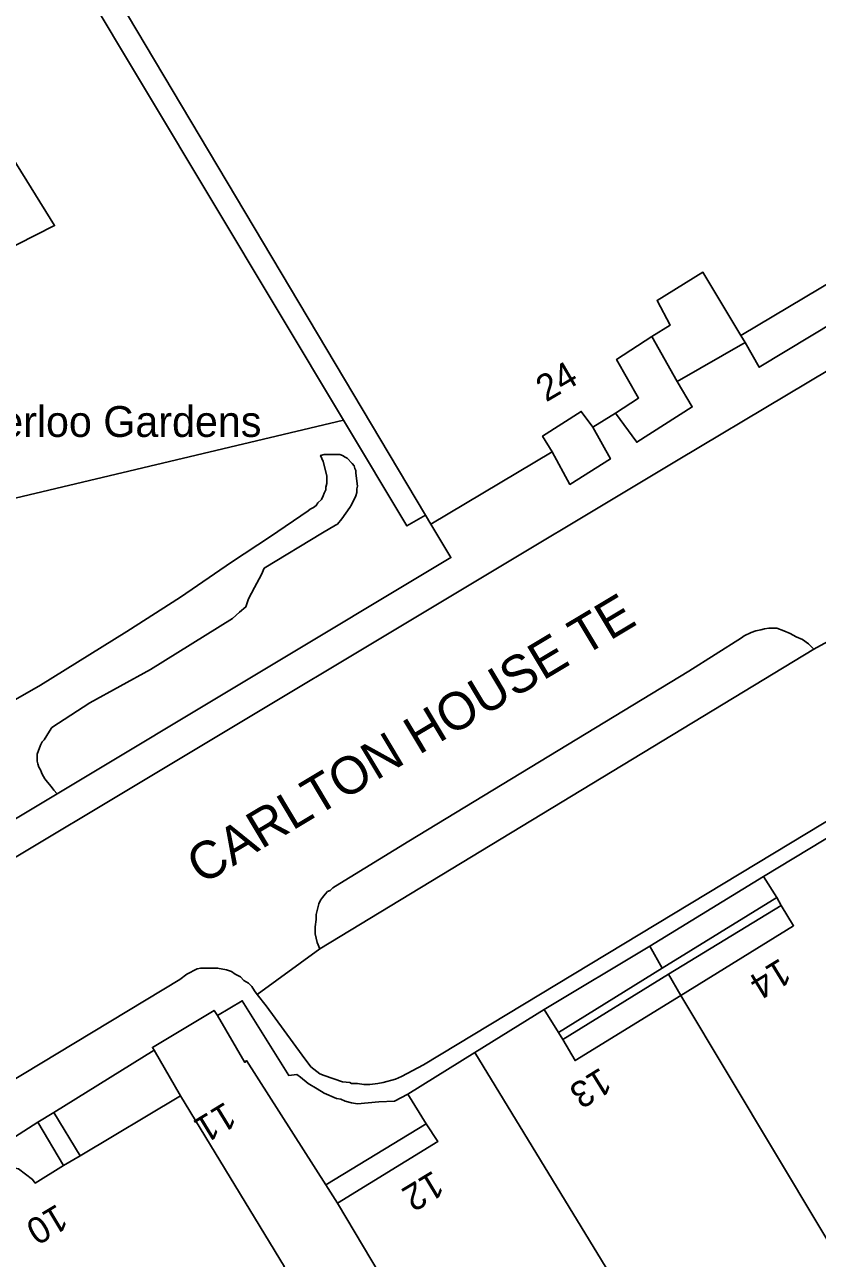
# Model space of a CAD drawing. Extents: x 529240 to 530363, y 179600 to 180767.
# Drawn here: x 529784.9 to 529829.9, y 180267.7 to 180337.8 of the extents above; entities that cross this region are included whole.
import ezdxf

# ---------------------------------------------------------------- set-up
doc = ezdxf.new("R2010")
doc.units = 0
for name, color, linetype in [('Building', 7, 'Continuous'), ('General surface', 7, 'Continuous'), ('Natural environment', 7, 'Continuous'), ('Path', 7, 'Continuous'), ('Road Or Track', 7, 'Continuous'), ('Roadside', 7, 'Continuous'), ('Unclassified', 7, 'Continuous')]:
    doc.layers.add(name, color=color, linetype=linetype)

msp = doc.modelspace()

# ---------------------------------------------------------------- linework, layer by layer
at = {"layer": 'Building'}
for points in [[(529789.25, 180340.9), (529788.1, 180340.25), (529803.05, 180315.3), (529806.65, 180309.3), (529807.7, 180309.9)], [(529825.85, 180319.7), (529826.65, 180318.3), (529855.6, 180335.75), (529854.55, 180337.35), (529825.6, 180320.1)], [(529817.2, 180314.9), (529816.55, 180315.8), (529814.35, 180314.4), (529814.9, 180313.5), (529815.9, 180311.65), (529818.2, 180313.1)], [(529852.9, 180277.1), (529842.1, 180294.8), (529836.25, 180291.25), (529835.6, 180292.45), (529834.6, 180294.05), (529826.9, 180289.4), (529827.65, 180288.2), (529827.9, 180287.75), (529828.6, 180286.6), (529822.2, 180282.65), (529832.9, 180264.8)], [(529822.2, 180282.65), (529828.6, 180286.6), (529827.9, 180287.75), (529821.5, 180283.85)], [(529822.2, 180282.65), (529821.5, 180283.85), (529815.5, 180280.15), (529816.2, 180278.95)], [(529832.9, 180264.8), (529822.2, 180282.65), (529816.2, 180278.95), (529815.5, 180280.15), (529815.25, 180280.55), (529814.45, 180281.85), (529810.5, 180279.4), (529823.05, 180258.85)], [(529792.3, 180279.55), (529793.8, 180276.95), (529799.7, 180267.25), (529793.15, 180263.3), (529796.35, 180258.05), (529798.2, 180259.2), (529799.2, 180257.45), (529802.85, 180259.65), (529804.05, 180257.6), (529805.3, 180258.4), (529806.8, 180256.05), (529809.1, 180257.45), (529808.35, 180258.7), (529809.5, 180259.45), (529802.7, 180270.85), (529802.05, 180271.9), (529797.55, 180278.95), (529797.45, 180278.85), (529795.9, 180281.5), (529795.7, 180281.8), (529792.2, 180279.7)], [(529813.45, 180252.9), (529823.05, 180258.85), (529810.5, 180279.4), (529806.7, 180277.05), (529807.75, 180275.35), (529808.4, 180274.35), (529802.7, 180270.85), (529809.5, 180259.45)], [(529802.05, 180271.9), (529802.7, 180270.85), (529808.4, 180274.35), (529807.75, 180275.35)]]:
    msp.add_lwpolyline(points, close=True, dxfattribs=at)
for points in [[(529789.25, 180340.9), (529807.7, 180309.9), (529808, 180309.4), (529814.9, 180313.5), (529814.35, 180314.4), (529816.55, 180315.8), (529817.2, 180314.9), (529818.5, 180315.7), (529819.8, 180316.55), (529818.55, 180318.75), (529820.55, 180320.05), (529821.6, 180320.7), (529820.85, 180322.1), (529823.45, 180323.7), (529825.6, 180320.1), (529854.55, 180337.35)], [(529789.25, 180340.9), (529807.7, 180309.9)], [(529825.6, 180320.1), (529854.55, 180337.35)], [(529825.85, 180319.7), (529826.65, 180318.3), (529855.6, 180335.75)], [(529820.55, 180320.05), (529821.6, 180320.7), (529820.85, 180322.1), (529823.45, 180323.7), (529825.6, 180320.1)], [(529818.5, 180315.7), (529819.8, 180316.55), (529818.55, 180318.75), (529820.55, 180320.05)], [(529825.6, 180320.1), (529825.85, 180319.7)], [(529814.9, 180313.5), (529814.35, 180314.4), (529816.55, 180315.8), (529817.2, 180314.9)], [(529817.2, 180314.9), (529818.5, 180315.7)], [(529808, 180309.4), (529814.9, 180313.5)], [(529807.7, 180309.9), (529808, 180309.4)], [(529826.9, 180289.4), (529834.6, 180294.05)], [(529827.65, 180288.2), (529826.9, 180289.4)], [(529827.9, 180287.75), (529827.65, 180288.2)], [(529821.5, 180283.85), (529827.9, 180287.75)], [(529822.2, 180282.65), (529828.6, 180286.6), (529827.9, 180287.75)], [(529821.5, 180283.85), (529815.5, 180280.15)], [(529822.2, 180282.65), (529821.5, 180283.85)], [(529815.5, 180280.15), (529816.2, 180278.95), (529822.2, 180282.65)], [(529832.9, 180264.8), (529822.2, 180282.65)], [(529795.7, 180281.8), (529792.2, 180279.7), (529792.3, 180279.55)], [(529795.7, 180281.8), (529795.9, 180281.5)], [(529795.9, 180281.5), (529797.45, 180278.85), (529797.55, 180278.95), (529802.05, 180271.9)], [(529814.45, 180281.85), (529810.5, 180279.4)], [(529815.25, 180280.55), (529814.45, 180281.85)], [(529815.5, 180280.15), (529815.25, 180280.55)], [(529792.3, 180279.55), (529793.8, 180276.95)], [(529810.5, 180279.4), (529806.7, 180277.05)], [(529810.5, 180279.4), (529823.05, 180258.85)], [(529799.7, 180267.25), (529793.8, 180276.95), (529788.1, 180273.55), (529787.15, 180273), (529785.55, 180272), (529785.4, 180272.2), (529784.6, 180272.8)], [(529793.8, 180276.95), (529788.1, 180273.55)], [(529793.8, 180276.95), (529799.7, 180267.25), (529793.15, 180263.3), (529796.35, 180258.05), (529798.2, 180259.2), (529799.2, 180257.45), (529802.85, 180259.65), (529804.05, 180257.6), (529805.3, 180258.4), (529806.8, 180256.05), (529809.1, 180257.45), (529808.35, 180258.7), (529809.5, 180259.45)], [(529806.7, 180277.05), (529807.75, 180275.35)], [(529802.05, 180271.9), (529807.75, 180275.35)], [(529807.75, 180275.35), (529808.4, 180274.35), (529802.7, 180270.85)], [(529787.15, 180273), (529785.55, 180272), (529785.4, 180272.2), (529784.6, 180272.8), (529784.4, 180272.85), (529784.2, 180272.95), (529783.95, 180273), (529783.6, 180273.1), (529783.3, 180273.15), (529782.75, 180273.15), (529782.55, 180273.45)], [(529788.1, 180273.55), (529787.15, 180273)], [(529802.05, 180271.9), (529802.7, 180270.85)], [(529802.7, 180270.85), (529809.5, 180259.45)]]:
    msp.add_lwpolyline(points, dxfattribs=at)
at = {"layer": 'General surface'}
for points in [[(529780.5, 180336.25), (529786.65, 180326.35), (529763.65, 180314.65), (529766.65, 180303.65), (529769.75, 180297.2), (529779.85, 180309.8), (529803.05, 180315.3), (529788.1, 180340.25), (529789.25, 180340.9), (529788.95, 180341.35), (529790.55, 180342.3), (529787.5, 180347), (529772.7, 180338.15)], [(529820.55, 180320.05), (529822, 180317.5), (529825.85, 180319.7), (529825.6, 180320.1), (529823.45, 180323.7), (529820.85, 180322.1), (529821.6, 180320.7)], [(529820.55, 180320.05), (529818.55, 180318.75), (529819.8, 180316.55), (529818.5, 180315.7), (529819.7, 180314.05), (529822.85, 180316.05), (529822, 180317.5)], [(529821.15, 180284.2), (529827.65, 180288.2), (529826.9, 180289.4), (529820.45, 180285.45)], [(529821.15, 180284.2), (529815.25, 180280.55), (529815.5, 180280.15), (529821.5, 180283.85), (529827.9, 180287.75), (529827.65, 180288.2)], [(529820.45, 180285.45), (529814.45, 180281.85), (529815.25, 180280.55), (529821.15, 180284.2)], [(529807.75, 180275.35), (529806.7, 180277.05), (529805.95, 180276.65), (529805.05, 180276.6), (529803.85, 180276.5), (529803.5, 180276.55), (529803.15, 180276.65), (529802.9, 180276.75), (529802.65, 180276.8), (529801.95, 180277.1), (529801.55, 180277.35), (529801.05, 180277.65), (529800.6, 180278), (529800.4, 180278.15), (529799.95, 180278.1), (529797.3, 180282.35), (529795.9, 180281.5), (529797.45, 180278.85), (529797.55, 180278.95), (529802.05, 180271.9)], [(529788.1, 180273.55), (529793.8, 180276.95), (529792.3, 180279.55), (529786.6, 180276)], [(529786.6, 180276), (529785.7, 180275.45), (529787.15, 180273), (529788.1, 180273.55)], [(529785.7, 180275.45), (529782.55, 180273.45), (529782.75, 180273.15), (529783.3, 180273.15), (529783.6, 180273.1), (529783.95, 180273), (529784.2, 180272.95), (529784.4, 180272.85), (529784.6, 180272.8), (529785.4, 180272.2), (529785.55, 180272), (529787.15, 180273)]]:
    msp.add_lwpolyline(points, close=True, dxfattribs=at)
for points in [[(529786.65, 180326.35), (529763.65, 180314.65), (529766.65, 180303.65), (529769.75, 180297.2), (529779.85, 180309.8), (529803.05, 180315.3)], [(529833.6, 180304.4), (529829.75, 180302.3), (529801.71, 180285.3), (529798.15, 180282.7), (529798.65, 180282.05), (529800.7, 180279.25), (529800.85, 180279.05), (529801.05, 180278.8), (529801.2, 180278.6), (529801.7, 180278.2), (529801.95, 180278.1), (529803, 180277.75), (529803.4, 180277.7), (529803.5, 180277.65), (529803.85, 180277.65), (529804.2, 180277.6), (529804.55, 180277.6), (529805, 180277.65), (529805.3, 180277.7), (529806, 180277.9), (529806.35, 180278.05), (529807.6, 180278.7), (529831.25, 180293)]]:
    msp.add_lwpolyline(points, dxfattribs=at)
at = {"layer": 'Natural environment'}
for points in [[(529763.65, 180314.65), (529786.65, 180326.35), (529780.5, 180336.25)], [(529781.9, 180298), (529785.85, 180300.25), (529790.75, 180303.3), (529793.8, 180305.25), (529796.7, 180307.25), (529798.9, 180308.7), (529801.05, 180310.15), (529801.15, 180310.25), (529801.35, 180310.35), (529801.5, 180310.45), (529801.6, 180310.6), (529801.8, 180310.8), (529801.9, 180311), (529801.95, 180311.15), (529802.05, 180311.35), (529802.05, 180311.5), (529802.1, 180311.7), (529802.1, 180312.15), (529801.9, 180312.95), (529801.75, 180313.3), (529801.95, 180313.35), (529802.85, 180313.35), (529803, 180313.3), (529803.15, 180313.2), (529803.25, 180313.15), (529803.55, 180312.85), (529803.65, 180312.7), (529803.7, 180312.55), (529803.75, 180312.45), (529803.75, 180312.3), (529803.85, 180311.55), (529803.8, 180311.4), (529803.8, 180311.2), (529803.75, 180311), (529803.5, 180310.5), (529803.4, 180310.35), (529802.95, 180309.7), (529802.7, 180309.4), (529802.6, 180309.35), (529801.85, 180308.9), (529798.55, 180306.9), (529798.4, 180306.55), (529798, 180305.8), (529797.65, 180305.15), (529797.5, 180304.7), (529797.15, 180304.4), (529796.75, 180304.05), (529792.1, 180301.15), (529788.65, 180299.25), (529786.5, 180297.85), (529786.35, 180297.65), (529786.05, 180297.15), (529785.95, 180297.05), (529785.85, 180296.85), (529785.65, 180296.35), (529785.65, 180295.95), (529785.7, 180295.8), (529785.75, 180295.6), (529785.85, 180295.45), (529785.9, 180295.3), (529785.95, 180295.2), (529786.1, 180294.95), (529786.25, 180294.75), (529786.45, 180294.5), (529786.6, 180294.3), (529786.8, 180294.1), (529809.15, 180307.5), (529808, 180309.4), (529807.7, 180309.9), (529806.65, 180309.3), (529803.05, 180315.3), (529779.85, 180309.8)]]:
    msp.add_lwpolyline(points, dxfattribs=at)
at = {"layer": 'Path'}
msp.add_lwpolyline([(529781.95, 180291.2), (529786.8, 180294.1), (529786.6, 180294.3), (529786.45, 180294.5), (529786.25, 180294.75), (529786.1, 180294.95), (529785.95, 180295.2), (529785.9, 180295.3), (529785.85, 180295.45), (529785.75, 180295.6), (529785.7, 180295.8), (529785.65, 180295.95), (529785.65, 180296.35), (529785.85, 180296.85), (529785.95, 180297.05), (529786.05, 180297.15), (529786.35, 180297.65), (529786.5, 180297.85), (529788.65, 180299.25), (529792.1, 180301.15), (529796.75, 180304.05), (529797.15, 180304.4), (529797.5, 180304.7), (529797.65, 180305.15), (529798, 180305.8), (529798.4, 180306.55), (529798.55, 180306.9), (529801.85, 180308.9), (529802.6, 180309.35), (529802.7, 180309.4), (529802.95, 180309.7), (529803.4, 180310.35), (529803.5, 180310.5), (529803.75, 180311), (529803.8, 180311.2), (529803.8, 180311.4), (529803.85, 180311.55), (529803.75, 180312.3), (529803.75, 180312.45), (529803.7, 180312.55), (529803.65, 180312.7), (529803.55, 180312.85), (529803.25, 180313.15), (529803.15, 180313.2), (529803, 180313.3), (529802.85, 180313.35), (529801.95, 180313.35), (529801.75, 180313.3), (529801.9, 180312.95), (529802.1, 180312.15), (529802.1, 180311.7), (529802.05, 180311.5), (529802.05, 180311.35), (529801.95, 180311.15), (529801.9, 180311), (529801.8, 180310.8), (529801.6, 180310.6), (529801.5, 180310.45), (529801.35, 180310.35), (529801.15, 180310.25), (529801.05, 180310.15), (529798.9, 180308.7), (529796.7, 180307.25), (529793.8, 180305.25), (529790.75, 180303.3), (529785.85, 180300.25), (529781.9, 180298)], dxfattribs=at)
at = {"layer": 'Road Or Track'}
for points in [[(529852.8, 180331.4), (529822.05, 180313.05), (529767, 180280.05)], [(529767, 180280.05), (529822.05, 180313.05), (529852.8, 180331.4)], [(529771.95, 180270.4), (529793.75, 180283.55), (529794.15, 180283.85), (529794.75, 180284.15), (529794.95, 180284.2), (529795.9, 180284.2), (529796.4, 180284.1), (529796.7, 180284), (529796.9, 180283.85), (529797.2, 180283.7), (529797.4, 180283.5), (529797.65, 180283.35), (529797.85, 180283.15), (529798, 180282.9), (529798.15, 180282.7), (529801.71, 180285.3), (529801.55, 180285.65), (529801.45, 180286.15), (529801.45, 180286.55), (529801.5, 180286.95), (529801.5, 180287.25), (529801.65, 180287.85), (529801.75, 180288.05), (529801.85, 180288.2), (529802, 180288.4), (529802.15, 180288.55), (529802.3, 180288.6), (529802.45, 180288.75), (529802.6, 180288.85), (529806.75, 180291.4), (529822.65, 180301.05), (529825.65, 180302.95), (529825.8, 180303.05), (529826.2, 180303.25), (529826.45, 180303.35), (529826.75, 180303.4), (529826.95, 180303.45), (529827.2, 180303.5), (529827.65, 180303.5), (529828.05, 180303.35), (529828.4, 180303.2), (529828.75, 180303), (529829.1, 180302.85), (529829.45, 180302.6), (529829.75, 180302.3), (529833.6, 180304.4)], [(529829.75, 180302.3), (529829.45, 180302.6), (529829.1, 180302.85), (529828.75, 180303), (529828.4, 180303.2), (529828.05, 180303.35), (529827.65, 180303.5), (529827.2, 180303.5), (529826.95, 180303.45), (529826.75, 180303.4), (529826.45, 180303.35), (529826.2, 180303.25), (529825.8, 180303.05), (529825.65, 180302.95), (529822.65, 180301.05), (529806.75, 180291.4), (529802.6, 180288.85), (529802.45, 180288.75), (529802.3, 180288.6), (529802.15, 180288.55), (529802, 180288.4), (529801.85, 180288.2), (529801.75, 180288.05), (529801.65, 180287.85), (529801.5, 180287.25), (529801.5, 180286.95), (529801.45, 180286.55), (529801.45, 180286.15), (529801.55, 180285.65), (529801.71, 180285.3)], [(529798.15, 180282.7), (529798, 180282.9), (529797.85, 180283.15), (529797.65, 180283.35), (529797.4, 180283.5), (529797.2, 180283.7), (529796.9, 180283.85), (529796.7, 180284), (529796.4, 180284.1), (529795.9, 180284.2), (529794.95, 180284.2), (529794.75, 180284.15), (529794.15, 180283.85), (529793.75, 180283.55), (529771.95, 180270.4), (529767.85, 180267.93)]]:
    msp.add_lwpolyline(points, dxfattribs=at)
at = {"layer": 'Roadside'}
for points in [[(529855.6, 180335.75), (529826.65, 180318.3), (529825.85, 180319.7), (529822, 180317.5), (529822.85, 180316.05), (529819.7, 180314.05), (529818.5, 180315.7), (529817.2, 180314.9), (529818.2, 180313.1), (529815.9, 180311.65), (529814.9, 180313.5), (529808, 180309.4), (529809.15, 180307.5), (529786.8, 180294.1), (529781.95, 180291.2)], [(529767, 180280.05), (529822.05, 180313.05), (529852.8, 180331.4)], [(529782.55, 180273.45), (529785.7, 180275.45), (529786.6, 180276), (529792.3, 180279.55), (529792.2, 180279.7), (529795.7, 180281.8), (529795.9, 180281.5), (529797.3, 180282.35), (529799.95, 180278.1), (529800.4, 180278.15), (529800.6, 180278), (529801.05, 180277.65), (529801.55, 180277.35), (529801.95, 180277.1), (529802.65, 180276.8), (529802.9, 180276.75), (529803.15, 180276.65), (529803.5, 180276.55), (529803.85, 180276.5), (529805.05, 180276.6), (529805.95, 180276.65), (529806.7, 180277.05), (529810.5, 180279.4), (529814.45, 180281.85), (529820.45, 180285.45), (529826.9, 180289.4), (529834.6, 180294.05)], [(529831.25, 180293), (529807.6, 180278.7), (529806.35, 180278.05), (529806, 180277.9), (529805.3, 180277.7), (529805, 180277.65), (529804.55, 180277.6), (529804.2, 180277.6), (529803.85, 180277.65), (529803.5, 180277.65), (529803.4, 180277.7), (529803, 180277.75), (529801.95, 180278.1), (529801.7, 180278.2), (529801.2, 180278.6), (529801.05, 180278.8), (529800.85, 180279.05), (529800.7, 180279.25), (529798.65, 180282.05), (529798.15, 180282.7), (529798, 180282.9), (529797.85, 180283.15), (529797.65, 180283.35), (529797.4, 180283.5), (529797.2, 180283.7), (529796.9, 180283.85), (529796.7, 180284), (529796.4, 180284.1), (529795.9, 180284.2), (529794.95, 180284.2), (529794.75, 180284.15), (529794.15, 180283.85), (529793.75, 180283.55), (529771.95, 180270.4)]]:
    msp.add_lwpolyline(points, dxfattribs=at)
msp.add_lwpolyline([(529801.71, 180285.3), (529829.75, 180302.3), (529829.45, 180302.6), (529829.1, 180302.85), (529828.75, 180303), (529828.4, 180303.2), (529828.05, 180303.35), (529827.65, 180303.5), (529827.2, 180303.5), (529826.95, 180303.45), (529826.75, 180303.4), (529826.45, 180303.35), (529826.2, 180303.25), (529825.8, 180303.05), (529825.65, 180302.95), (529822.65, 180301.05), (529806.75, 180291.4), (529802.6, 180288.85), (529802.45, 180288.75), (529802.3, 180288.6), (529802.15, 180288.55), (529802, 180288.4), (529801.85, 180288.2), (529801.75, 180288.05), (529801.65, 180287.85), (529801.5, 180287.25), (529801.5, 180286.95), (529801.45, 180286.55), (529801.45, 180286.15), (529801.55, 180285.65)], close=True, dxfattribs=at)
at = {"layer": 'Unclassified'}
for points in [[(529789.25, 180340.9), (529788.1, 180340.25), (529803.05, 180315.3)], [(529780.5, 180336.25), (529786.65, 180326.35)], [(529822, 180317.5), (529820.55, 180320.05)], [(529822, 180317.5), (529825.85, 180319.7)], [(529818.5, 180315.7), (529819.7, 180314.05), (529822.85, 180316.05), (529822, 180317.5)], [(529803.05, 180315.3), (529806.65, 180309.3), (529807.7, 180309.9)], [(529814.9, 180313.5), (529815.9, 180311.65), (529818.2, 180313.1), (529817.2, 180314.9)], [(529779.1, 180297.15), (529780.2, 180297), (529781.9, 180298), (529785.85, 180300.25), (529790.75, 180303.3), (529793.8, 180305.25), (529796.7, 180307.25), (529798.9, 180308.7), (529801.05, 180310.15), (529801.15, 180310.25), (529801.35, 180310.35), (529801.5, 180310.45), (529801.6, 180310.6), (529801.8, 180310.8), (529801.9, 180311), (529801.95, 180311.15), (529802.05, 180311.35), (529802.05, 180311.5), (529802.1, 180311.7), (529802.1, 180312.15), (529801.9, 180312.95), (529801.75, 180313.3)], [(529801.75, 180313.3), (529801.95, 180313.35), (529802.85, 180313.35), (529803, 180313.3), (529803.15, 180313.2), (529803.25, 180313.15), (529803.55, 180312.85), (529803.65, 180312.7), (529803.7, 180312.55), (529803.75, 180312.45), (529803.75, 180312.3), (529803.85, 180311.55), (529803.8, 180311.4), (529803.8, 180311.2), (529803.75, 180311), (529803.5, 180310.5), (529803.4, 180310.35), (529802.95, 180309.7), (529802.7, 180309.4), (529802.6, 180309.35), (529801.85, 180308.9), (529798.55, 180306.9), (529798.4, 180306.55), (529798, 180305.8), (529797.65, 180305.15), (529797.5, 180304.7), (529797.15, 180304.4), (529796.75, 180304.05), (529792.1, 180301.15), (529788.65, 180299.25), (529786.5, 180297.85), (529786.35, 180297.65), (529786.05, 180297.15), (529785.95, 180297.05), (529785.85, 180296.85), (529785.65, 180296.35), (529785.65, 180295.95), (529785.7, 180295.8), (529785.75, 180295.6), (529785.85, 180295.45), (529785.9, 180295.3), (529785.95, 180295.2), (529786.1, 180294.95), (529786.25, 180294.75), (529786.45, 180294.5), (529786.6, 180294.3), (529786.8, 180294.1)], [(529786.8, 180294.1), (529809.15, 180307.5), (529808, 180309.4)], [(529829.75, 180302.3), (529833.6, 180304.4)], [(529829.75, 180302.3), (529801.71, 180285.3)], [(529781.95, 180291.2), (529786.8, 180294.1)], [(529831.25, 180293), (529807.6, 180278.7), (529806.35, 180278.05), (529806, 180277.9), (529805.3, 180277.7), (529805, 180277.65), (529804.55, 180277.6), (529804.2, 180277.6), (529803.85, 180277.65), (529803.5, 180277.65), (529803.4, 180277.7), (529803, 180277.75), (529801.95, 180278.1), (529801.7, 180278.2), (529801.2, 180278.6), (529801.05, 180278.8), (529800.85, 180279.05), (529800.7, 180279.25), (529798.65, 180282.05), (529798.15, 180282.7)], [(529826.9, 180289.4), (529820.45, 180285.45)], [(529821.15, 180284.2), (529827.65, 180288.2)], [(529798.15, 180282.7), (529801.71, 180285.3)], [(529820.45, 180285.45), (529814.45, 180281.85)], [(529820.45, 180285.45), (529821.15, 180284.2)], [(529815.25, 180280.55), (529821.15, 180284.2)], [(529795.9, 180281.5), (529797.3, 180282.35), (529799.95, 180278.1), (529800.4, 180278.15), (529800.6, 180278), (529801.05, 180277.65), (529801.55, 180277.35), (529801.95, 180277.1), (529802.65, 180276.8), (529802.9, 180276.75), (529803.15, 180276.65), (529803.5, 180276.55), (529803.85, 180276.5), (529805.05, 180276.6), (529805.95, 180276.65), (529806.7, 180277.05)], [(529792.3, 180279.55), (529786.6, 180276)], [(529786.6, 180276), (529785.7, 180275.45)], [(529786.6, 180276), (529788.1, 180273.55)], [(529785.7, 180275.45), (529782.55, 180273.45)], [(529785.7, 180275.45), (529787.15, 180273)]]:
    msp.add_lwpolyline(points, dxfattribs=at)

# ---------------------------------------------------------------- texts
at = {"layer": 'General surface'}
msp.add_text('Waterloo Gardens', height=1.75, dxfattribs=at).set_placement((529779.4, 180314.35))
at = {"layer": 'Road Or Track'}
msp.add_text('CARLTON HOUSE TE', height=2.125, rotation=30.9, dxfattribs=at).set_placement((529795, 180288.9))
at = {"layer": 'Unclassified'}
for s, rotation, p in [('24', 30.3, (529814.55, 180316.3)), ('14', 211.5, (529827.85, 180284.8)), ('13', 211.8, (529817.65, 180278.6)), ('11', 211.4, (529796.35, 180276.65)), ('12', 211.2, (529808.15, 180272.75)), ('10', 211, (529786.8, 180270.85))]:
    msp.add_text(s, height=1.5, rotation=rotation, dxfattribs=at).set_placement(p)

doc.saveas('drawing.dxf')
